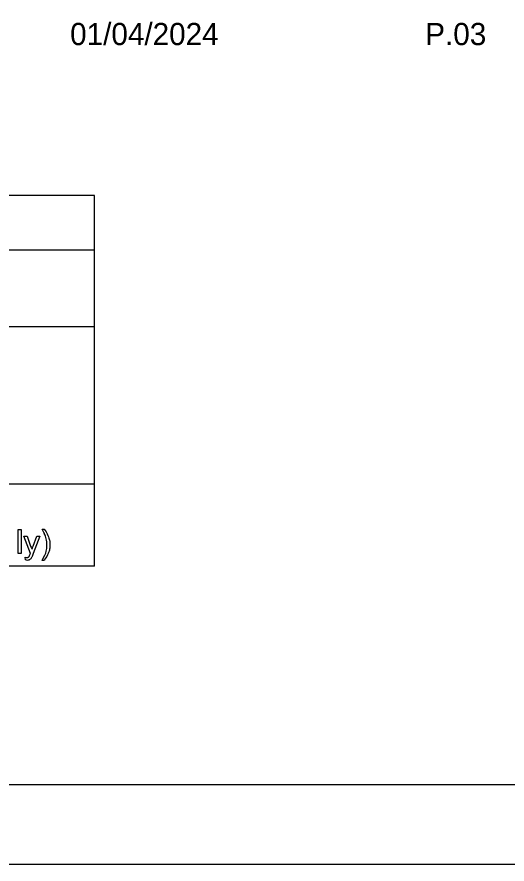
# Model space of a CAD drawing. Extents: x -3.6 to 34, y 0 to 32.8.
# Drawn here: x 6.14 to 9.23, y 0 to 5.34 of the extents above; entities that cross this region are included whole.
import ezdxf

# ---------------------------------------------------------------- set-up
doc = ezdxf.new("R2010")
doc.units = 0
for name, color, linetype in [('SH_Border', 7, 'Continuous'), ('SH_Cut_Line', 7, 'Continuous'), ('SH_Data', 7, 'Continuous'), ('SH_Text', 7, 'Continuous')]:
    doc.layers.add(name, color=color, linetype=linetype)

msp = doc.modelspace()

# ---------------------------------------------------------------- linework, layer by layer
at = {"layer": 'SH_Border'}
msp.add_lwpolyline([(1.5, 21.5), (33.5, 21.5), (33.5, 0.5), (1.5, 0.5)], close=True, dxfattribs=at)
at = {"layer": 'SH_Cut_Line'}
msp.add_lwpolyline([(0, 0), (34, 0), (34, 22), (0, 22)], close=True, dxfattribs=at)
at = {"layer": 'SH_Data'}
for p, q in [((6.6275, 4.216), (2.3775, 4.216)), ((6.6275, 1.8785), (6.6275, 4.216)), ((2.3775, 3.8744), (6.6275, 3.8744)), ((2.3775, 3.391), (6.6275, 3.391)), ((6.6275, 2.3964), (2.3775, 2.3964)), ((6.6275, 1.8785), (2.3775, 1.8785))]:
    msp.add_line(p, q, dxfattribs=at)
at = {"layer": 'SH_Text'}
for points in [[(6.1465, 1.9596), (6.1465, 2.1098), (6.1649, 2.1098), (6.1649, 1.9596), (6.1465, 1.9596)], [(6.2974, 2.1123), (6.3105, 2.1123)], [(6.2243, 1.9596), (6.183, 2.0685), (6.2029, 2.0685), (6.2255, 2.0057)], [(6.241, 2.005), (6.2643, 2.0685), (6.2827, 2.0685), (6.2414, 1.9577)], [(6.1928, 1.9178), (6.1907, 1.9352)], [(6.3105, 1.9155), (6.2974, 1.9155)]]:
    msp.add_lwpolyline(points, dxfattribs=at)
for points in [[(6.2974, 1.9155), (6.3279, 1.9646), (6.3279, 2.0139), (6.3279, 2.0331), (6.3235, 2.0521), (6.32, 2.0675), (6.3138, 2.0816), (6.3098, 2.0908), (6.2974, 2.1123)], [(6.3105, 2.1123), (6.3298, 2.0866), (6.339, 2.0607), (6.3469, 2.0384), (6.3469, 2.014), (6.3469, 1.9863), (6.3363, 1.9605), (6.3257, 1.9347), (6.3105, 1.9155)], [(6.2255, 2.0057), (6.2299, 1.9937), (6.2334, 1.9805), (6.2366, 1.9929), (6.241, 2.005)], [(6.1907, 1.9352), (6.1967, 1.9335), (6.2012, 1.9335), (6.2074, 1.9335), (6.211, 1.9356), (6.2147, 1.9376), (6.2171, 1.9413), (6.2188, 1.9441), (6.2227, 1.955), (6.2232, 1.9566), (6.2243, 1.9596)], [(6.2414, 1.9577), (6.2348, 1.9399), (6.2311, 1.9331), (6.2262, 1.9241), (6.2198, 1.9198), (6.2135, 1.9156), (6.2046, 1.9156), (6.1993, 1.9156), (6.1928, 1.9178)]]:
    msp.add_open_spline(points, degree=3, dxfattribs=at)

# ---------------------------------------------------------------- texts
for s, p in [('01/04/2024', (6.4744, 5.1652)), ('P.03', (8.7144, 5.1652))]:
    msp.add_text(s, height=0.14, dxfattribs=at).set_placement(p)

doc.saveas('drawing.dxf')
